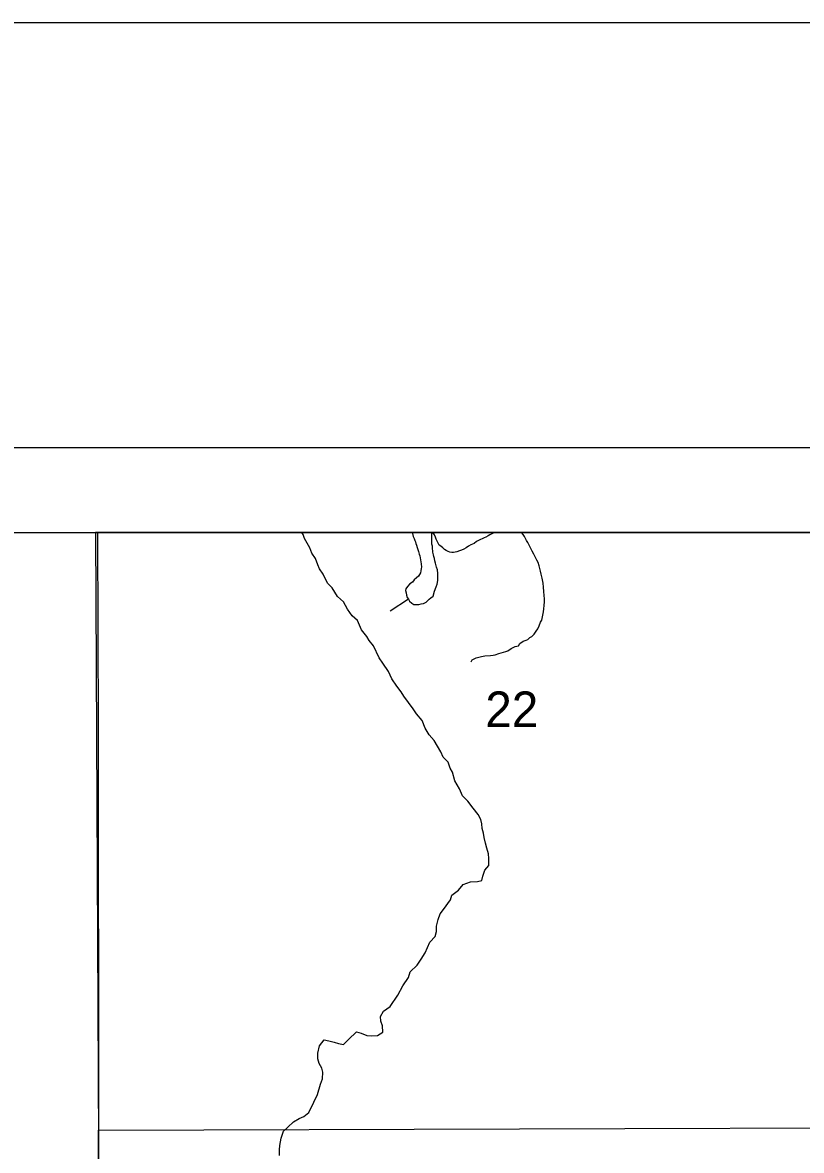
# Model space of a CAD drawing. Extents: x -10.1 to 68, y -9.5 to 29.2.
# Drawn here: x 6.404 to 7.321, y 20.173 to 21.5 of the extents above; entities that cross this region are included whole.
import ezdxf

# ---------------------------------------------------------------- set-up
doc = ezdxf.new("R2010")
doc.units = 0
for name, color, linetype in [('GM_X_Major_Lake', 7, 'Continuous'), ('GM_X_Major_River', 7, 'Continuous'), ('GM_X_Minor_River', 7, 'Continuous'), ('GM_X_Section', 7, 'Continuous'), ('GM_X_Section_Text', 7, 'Continuous'), ('GM_X_Township', 7, 'Continuous'), ('SH_Border', 7, 'Continuous'), ('SH_Data', 7, 'Continuous')]:
    doc.layers.add(name, color=color, linetype=linetype)

msp = doc.modelspace()

# ---------------------------------------------------------------- linework, layer by layer
at = {"layer": 'GM_X_Major_Lake'}
for points in [[(6.9403, 20.5681), (6.9346, 20.5757), (6.9281, 20.5837), (6.9221, 20.5901), (6.9186, 20.5981), (6.913, 20.6076), (6.9103, 20.6179), (6.9073, 20.6228), (6.905, 20.6296), (6.8993, 20.6357), (6.8966, 20.6418), (6.8887, 20.6551), (6.8826, 20.6619), (6.8781, 20.6695), (6.8746, 20.6786), (6.8678, 20.6866), (6.864, 20.6923), (6.8583, 20.6998), (6.853, 20.7074), (6.8496, 20.7124), (6.8447, 20.7192), (6.839, 20.7279), (6.8348, 20.7363), (6.8284, 20.7462), (6.8238, 20.7526), (6.8174, 20.7667), (6.8121, 20.7727), (6.8094, 20.7777), (6.8033, 20.7852), (6.7984, 20.7963), (6.7923, 20.802), (6.7867, 20.8099), (6.7821, 20.8183), (6.7749, 20.8247), (6.7688, 20.835), (6.7631, 20.8403), (6.7582, 20.8509), (6.7537, 20.857), (6.7518, 20.8619), (6.7491, 20.8695), (6.7446, 20.8756), (6.7423, 20.882), (6.7362, 20.8927), (6.7343, 20.8976), (6.7328, 20.9)], [(6.7068, 20.1667), (6.7068, 20.1735), (6.7072, 20.1785), (6.7087, 20.1872), (6.7114, 20.1956), (6.7163, 20.2001), (6.7231, 20.2066), (6.7296, 20.2104), (6.7353, 20.2127), (6.741, 20.2176), (6.7471, 20.2294), (6.7512, 20.2385), (6.755, 20.2507), (6.7573, 20.2572), (6.7577, 20.2648), (6.7566, 20.2697), (6.7535, 20.275), (6.7516, 20.2807), (6.7516, 20.2872), (6.7539, 20.2959), (6.7592, 20.3028), (6.7645, 20.3016), (6.771, 20.3001), (6.7759, 20.2986), (6.782, 20.2975), (6.788, 20.3032), (6.7972, 20.3123), (6.8028, 20.3108), (6.8093, 20.3081), (6.8146, 20.3078), (6.8218, 20.3081), (6.8283, 20.312), (6.8279, 20.3196), (6.826, 20.3249), (6.8256, 20.3302), (6.829, 20.3366), (6.837, 20.342), (6.8457, 20.3553), (6.8518, 20.3663), (6.8583, 20.3762), (6.8602, 20.383), (6.8685, 20.3906), (6.8734, 20.3979), (6.878, 20.4055), (6.8837, 20.418), (6.8898, 20.4245), (6.8913, 20.4306), (6.8913, 20.4366), (6.8932, 20.4446), (6.8955, 20.4511), (6.8996, 20.4564), (6.908, 20.4678), (6.9095, 20.4731), (6.9171, 20.4792), (6.9228, 20.4857), (6.9315, 20.4887), (6.9395, 20.4891), (6.9448, 20.4906), (6.9459, 20.4956), (6.9482, 20.5024), (6.9528, 20.5081), (6.9528, 20.5165), (6.9524, 20.5218), (6.9505, 20.5286), (6.949, 20.5343), (6.9475, 20.5412), (6.9467, 20.5461), (6.9452, 20.5518), (6.9448, 20.5571), (6.9437, 20.5621)], [(6.9437, 20.5621), (6.9403, 20.5681)]]:
    msp.add_lwpolyline(points, dxfattribs=at)
at = {"layer": 'GM_X_Major_River'}
for points in [[(6.9403, 20.5681), (6.9346, 20.5757), (6.9281, 20.5837), (6.9221, 20.5901), (6.9186, 20.5981), (6.913, 20.6076), (6.9103, 20.6179), (6.9073, 20.6228), (6.905, 20.6296), (6.8993, 20.6357), (6.8966, 20.6418), (6.8887, 20.6551), (6.8826, 20.6619), (6.8781, 20.6695), (6.8746, 20.6786), (6.8678, 20.6866), (6.864, 20.6923), (6.8583, 20.6998), (6.853, 20.7074), (6.8496, 20.7124), (6.8447, 20.7192), (6.839, 20.7279), (6.8348, 20.7363), (6.8284, 20.7462), (6.8238, 20.7526), (6.8174, 20.7667), (6.8121, 20.7727), (6.8094, 20.7777), (6.8033, 20.7852), (6.7984, 20.7963), (6.7923, 20.802), (6.7867, 20.8099), (6.7821, 20.8183), (6.7749, 20.8247), (6.7688, 20.835), (6.7631, 20.8403), (6.7582, 20.8509), (6.7537, 20.857), (6.7518, 20.8619), (6.7491, 20.8695), (6.7446, 20.8756), (6.7423, 20.882), (6.7362, 20.8927), (6.7343, 20.8976), (6.7328, 20.9)], [(6.8631, 20.9), (6.8633, 20.8986), (6.8641, 20.8952), (6.865, 20.893), (6.8658, 20.8907), (6.8666, 20.8888), (6.867, 20.8869), (6.8678, 20.885), (6.8686, 20.8824), (6.8694, 20.8801), (6.8702, 20.8775), (6.8711, 20.8745), (6.8719, 20.8726), (6.8723, 20.8703), (6.8727, 20.8677), (6.8731, 20.8654), (6.8732, 20.8631), (6.8737, 20.8593), (6.8733, 20.8574), (6.873, 20.8547), (6.8727, 20.8525), (6.8701, 20.8486), (6.8678, 20.8467), (6.8652, 20.8443), (6.863, 20.8416), (6.86, 20.8396), (6.8574, 20.8365), (6.8552, 20.8338), (6.8549, 20.8315), (6.8557, 20.8289), (6.8561, 20.8263), (6.8569, 20.8236), (6.8585, 20.8214), (6.8597, 20.8191), (6.8624, 20.8169), (6.8647, 20.8154), (6.8666, 20.8151), (6.8704, 20.8152), (6.8734, 20.816), (6.8761, 20.8164), (6.8791, 20.818), (6.8828, 20.8215), (6.8847, 20.8231), (6.8873, 20.825), (6.8891, 20.8308), (6.8909, 20.8358), (6.8923, 20.8392), (6.893, 20.8434), (6.8929, 20.848), (6.8928, 20.8518), (6.8924, 20.8559), (6.8915, 20.8593), (6.8903, 20.8639), (6.8895, 20.8665), (6.889, 20.8695), (6.8882, 20.8718), (6.8878, 20.8737), (6.887, 20.8767), (6.8869, 20.8786), (6.8865, 20.8805), (6.8865, 20.8839), (6.886, 20.8862), (6.886, 20.8892), (6.8859, 20.8919), (6.8858, 20.8946), (6.8858, 20.8972), (6.8857, 20.9)], [(6.7068, 20.1667), (6.7068, 20.1735), (6.7072, 20.1785), (6.7087, 20.1872), (6.7114, 20.1956), (6.7163, 20.2001), (6.7231, 20.2066), (6.7296, 20.2104), (6.7353, 20.2127), (6.741, 20.2176), (6.7471, 20.2294), (6.7512, 20.2385), (6.755, 20.2507), (6.7573, 20.2572), (6.7577, 20.2648), (6.7566, 20.2697), (6.7535, 20.275), (6.7516, 20.2807), (6.7516, 20.2872), (6.7539, 20.2959), (6.7592, 20.3028), (6.7645, 20.3016), (6.771, 20.3001), (6.7759, 20.2986), (6.782, 20.2975), (6.788, 20.3032), (6.7972, 20.3123), (6.8028, 20.3108), (6.8093, 20.3081), (6.8146, 20.3078), (6.8218, 20.3081), (6.8283, 20.312), (6.8279, 20.3196), (6.826, 20.3249), (6.8256, 20.3302), (6.829, 20.3366), (6.837, 20.342), (6.8457, 20.3553), (6.8518, 20.3663), (6.8583, 20.3762), (6.8602, 20.383), (6.8685, 20.3906), (6.8734, 20.3979), (6.878, 20.4055), (6.8837, 20.418), (6.8898, 20.4245), (6.8913, 20.4306), (6.8913, 20.4366), (6.8932, 20.4446), (6.8955, 20.4511), (6.8996, 20.4564), (6.908, 20.4678), (6.9095, 20.4731), (6.9171, 20.4792), (6.9228, 20.4857), (6.9315, 20.4887), (6.9395, 20.4891), (6.9448, 20.4906), (6.9459, 20.4956), (6.9482, 20.5024), (6.9528, 20.5081), (6.9528, 20.5165), (6.9524, 20.5218), (6.9505, 20.5286), (6.949, 20.5343), (6.9475, 20.5412), (6.9467, 20.5461), (6.9452, 20.5518), (6.9448, 20.5571), (6.9437, 20.5621)], [(6.9437, 20.5621), (6.9403, 20.5681)]]:
    msp.add_lwpolyline(points, dxfattribs=at)
at = {"layer": 'GM_X_Minor_River'}
msp.add_line((6.8585, 20.8214), (6.837, 20.8075), dxfattribs=at)
for points in [[(6.9593, 20.9), (6.9573, 20.8988), (6.9543, 20.8972), (6.952, 20.896), (6.9494, 20.8944), (6.9475, 20.8936), (6.9452, 20.8924), (6.943, 20.8916), (6.9407, 20.8904), (6.9385, 20.8892), (6.9358, 20.8869), (6.9317, 20.8853), (6.9291, 20.8837), (6.9264, 20.8818), (6.9234, 20.8802), (6.9208, 20.879), (6.9185, 20.8785), (6.9151, 20.8773), (6.9132, 20.8769), (6.9113, 20.8765), (6.9094, 20.8764), (6.9071, 20.8768), (6.9052, 20.8775), (6.9029, 20.8786), (6.9006, 20.88), (6.8987, 20.8819), (6.8963, 20.8838), (6.8944, 20.8852), (6.8908, 20.892), (6.89, 20.8946), (6.8892, 20.8973), (6.8871, 20.9)], [(6.932, 20.7477), (6.9334, 20.75), (6.9379, 20.7524), (6.9444, 20.7541), (6.9482, 20.7549), (6.955, 20.7551), (6.958, 20.7555), (6.9603, 20.7559), (6.9645, 20.7576), (6.9675, 20.7584), (6.9701, 20.7592), (6.9728, 20.76), (6.9754, 20.7608), (6.9792, 20.7636), (6.9841, 20.7656), (6.9879, 20.7664), (6.9893, 20.7695), (6.9934, 20.7719), (6.9968, 20.7731), (6.9987, 20.7739), (7.0013, 20.7762), (7.0036, 20.7774), (7.0062, 20.7801), (7.0088, 20.784), (7.0106, 20.7867), (7.0121, 20.7901), (7.0139, 20.7944), (7.0154, 20.7967), (7.0164, 20.8028), (7.0171, 20.8066), (7.0177, 20.81), (7.018, 20.8142), (7.0183, 20.8184), (7.0183, 20.8218), (7.0182, 20.8256), (7.0177, 20.8305), (7.0172, 20.8355), (7.0167, 20.8404), (7.0158, 20.8461), (7.0146, 20.851), (7.0138, 20.8544), (7.0129, 20.8574), (7.0121, 20.8608), (7.0109, 20.8646), (7.0093, 20.8672), (7.0077, 20.8706), (7.0057, 20.8744), (7.0041, 20.8778), (7.0022, 20.8811), (7.0005, 20.8849), (6.999, 20.8883), (6.9974, 20.8905), (6.9962, 20.8928), (6.995, 20.8954), (6.9934, 20.8977), (6.9915, 20.8999), (6.9914, 20.9)]]:
    msp.add_lwpolyline(points, dxfattribs=at)
at = {"layer": 'GM_X_Section'}
msp.add_line((7.4658, 20.9), (6.4927, 20.9), dxfattribs=at)
msp.add_lwpolyline([(6.4927, 20.9), (6.4934, 20.6709), (6.4939, 20.1965), (7.4845, 20.1996), (7.4658, 20.9)], dxfattribs=at)
msp.add_lwpolyline([(6.4939, 20.1965), (7.4845, 20.1996), (7.4884, 19.0658), (6.4989, 19.0557)], close=True, dxfattribs=at)
at = {"layer": 'GM_X_Township'}
for points in [[(8.9, 16.8967), (8.9, 20.9), (6.49, 20.9)], [(6.49, 20.9), (6.4976, 19.3842), (6.5141, 17.4202), (6.5083, 16.8667), (7.5233, 16.8774), (7.9665, 16.8821), (8.5023, 16.8904), (8.9, 16.8967)]]:
    msp.add_lwpolyline(points, dxfattribs=at)
at = {"layer": 'SH_Border'}
msp.add_lwpolyline([(1.5, 21.5), (33.5, 21.5), (33.5, 0.5), (1.5, 0.5)], close=True, dxfattribs=at)
at = {"layer": 'SH_Data'}
for p, q in [((2, 21), (9, 21)), ((2.1, 20.9), (8.9, 20.9))]:
    msp.add_line(p, q, dxfattribs=at)

# ---------------------------------------------------------------- texts
at = {"layer": 'GM_X_Section_Text'}
msp.add_text('22', height=0.04186, rotation=0, dxfattribs=at).set_placement((6.9488, 20.671))

doc.saveas('drawing.dxf')
